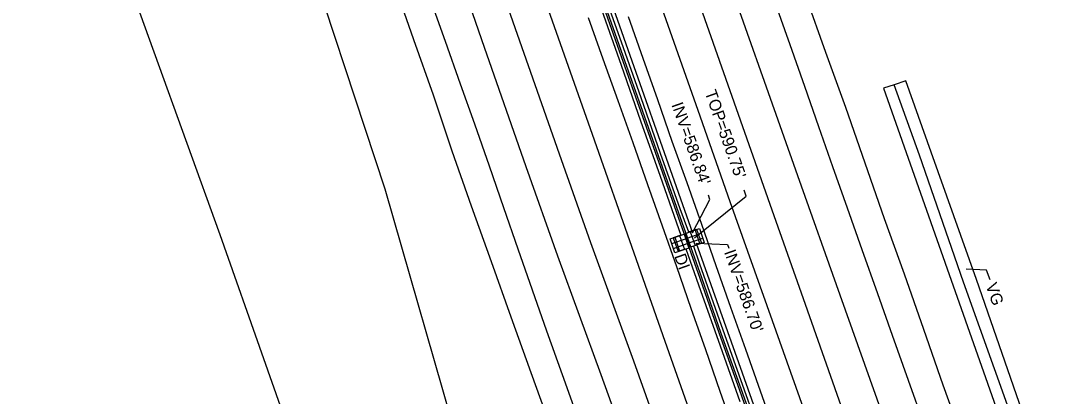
# Model space of a CAD drawing. Extents: x 2004847 to 2009016, y 1134161 to 1140101.
# Drawn here: x 2005569.8 to 2005919.4, y 1137430.7 to 1137558.5 of the extents above; entities that cross this region are included whole.
import ezdxf

# ---------------------------------------------------------------- set-up
doc = ezdxf.new("R2010")
doc.units = 0
for name, color, linetype in [('RD_EX_Conc', 7, 'Continuous'), ('RD_EX_DR_Inlet', 7, 'Continuous'), ('RD_EX_DR_Inlet_txCode', 7, 'Continuous'), ('RD_EX_DR_Pipe', 7, 'Continuous'), ('RD_EX_Fence_Other', 7, 'Continuous'), ('RD_EX_Pavement_Markings', 7, 'Continuous'), ('RD_EX_Road', 7, 'Continuous'), ('RD_EX_VEG', 7, 'Continuous'), ('RD_Sketch3', 7, 'Continuous')]:
    doc.layers.add(name, color=color, linetype=linetype)

msp = doc.modelspace()

# ---------------------------------------------------------------- linework, layer by layer
at = {"layer": 'RD_EX_Conc'}
for points in [[(2005680.52, 1137810.28), (2005687.18, 1137791.43), (2005693.85, 1137772.58), (2005700.54, 1137753.73), (2005707.21, 1137734.88), (2005713.85, 1137716.01), (2005720.48, 1137697.14), (2005727.14, 1137678.29), (2005733.79, 1137659.43), (2005740.49, 1137640.59), (2005747.16, 1137621.74), (2005753.85, 1137602.89), (2005760.49, 1137584.03), (2005767.18, 1137565.18), (2005773.87, 1137546.33), (2005780.5, 1137527.47), (2005787.18, 1137508.62), (2005793.87, 1137489.77), (2005800.53, 1137470.92), (2005807.19, 1137452.06), (2005813.89, 1137433.22), (2005820.56, 1137414.37)], [(2005681.18, 1137810.52), (2005687.84, 1137791.67), (2005694.51, 1137772.82), (2005701.21, 1137753.96), (2005707.88, 1137735.11), (2005714.51, 1137716.25), (2005721.16, 1137697.38), (2005727.78, 1137678.52), (2005734.42, 1137659.66), (2005741.13, 1137640.82), (2005747.79, 1137621.96), (2005754.44, 1137603.1), (2005761.08, 1137584.24), (2005767.77, 1137565.39), (2005774.43, 1137546.53), (2005781.07, 1137527.67), (2005787.74, 1137508.82), (2005794.43, 1137489.97), (2005801.1, 1137471.13), (2005807.76, 1137452.26), (2005814.47, 1137433.43), (2005821.16, 1137414.58)], [(2005966.12, 1137270.11), (2005960.31, 1137284.97), (2005945.18, 1137326.1), (2005939.36, 1137342.34), (2005925.51, 1137382.31), (2005910.14, 1137425.7), (2005894.53, 1137470.45), (2005879.23, 1137513.74), (2005870.52, 1137538.02), (2005866.6, 1137536.67), (2005863.03, 1137535.48)], [(2005863.03, 1137535.48), (2005871.4, 1137511.75), (2005886.7, 1137468.35), (2005902.54, 1137423.33), (2005917.98, 1137379.04), (2005930.59, 1137344.77), (2005930.07, 1137344.38), (2005930.61, 1137342.05), (2005930.73, 1137340.06), (2005932.46, 1137338.07), (2005937.59, 1137323.83), (2005952.48, 1137282.46), (2005970.17, 1137237.5), (2005987.63, 1137193.19), (2006006.12, 1137147.67), (2006025.01, 1137102.92)]]:
    msp.add_lwpolyline(points, dxfattribs=at)
at = {"layer": 'RD_EX_DR_Inlet'}
for p, q in [((2005797.35, 1137486.7), (2005798.97, 1137481.98)), ((2005798.95, 1137487.26), (2005800.58, 1137482.53)), ((2005791.03, 1137482.67), (2005795.76, 1137484.29)), ((2005792.09, 1137484.83), (2005793.71, 1137480.1)), ((2005793.69, 1137485.38), (2005795.32, 1137480.65)), ((2005796.29, 1137484.55), (2005801.02, 1137486.17)), ((2005796.84, 1137482.94), (2005801.57, 1137484.56)), ((2005791.58, 1137481.06), (2005796.31, 1137482.69))]:
    msp.add_line(p, q, dxfattribs=at)
for points in [[(2005797.36, 1137481.42), (2005795.74, 1137486.15), (2005800.47, 1137487.78), (2005802.09, 1137483.05)], [(2005792.1, 1137479.55), (2005790.48, 1137484.28), (2005795.21, 1137485.9), (2005796.83, 1137481.17)]]:
    msp.add_lwpolyline(points, close=True, dxfattribs=at)
at = {"layer": 'RD_EX_DR_Inlet_txCode'}
for points in [[(2005798.74, 1137484.62), (2005816.32, 1137498.83), (2005815.62, 1137500.8)], [(2005798.12, 1137486.36), (2005804.03, 1137497.65), (2005803.52, 1137499.1)], [(2005799.38, 1137482.87), (2005810.03, 1137482.31), (2005810.44, 1137481.16)]]:
    msp.add_lwpolyline(points, dxfattribs=at)
at = {"layer": 'RD_EX_DR_Pipe'}
for p, q in [((2005736.5, 1137660.69), (2005798.12, 1137486.36)), ((2005799.38, 1137482.87), (2005860.99, 1137308.79))]:
    msp.add_line(p, q, dxfattribs=at)
at = {"layer": 'RD_EX_Fence_Other'}
msp.add_lwpolyline([(2005544.1, 1137747.93), (2005571.98, 1137669.9), (2005603.8, 1137579.06), (2005637.48, 1137485.82), (2005667.17, 1137401.41)], dxfattribs=at)
at = {"layer": 'RD_EX_Pavement_Markings'}
for points in [[(2005650.65, 1138023.79), (2005661.36, 1137993.16), (2005675.57, 1137952.57), (2005689.8, 1137912.08), (2005700.62, 1137881.25), (2005715.02, 1137840.66), (2005729.45, 1137800.21), (2005740.39, 1137769.42), (2005754.76, 1137728.86), (2005769.14, 1137688.32), (2005780.1, 1137657.44), (2005794.53, 1137616.94), (2005808.89, 1137576.39), (2005823.14, 1137536.02), (2005833.8, 1137505.87), (2005848.16, 1137465.29), (2005862.54, 1137424.75)], [(2005638.93, 1138020.85), (2005649.77, 1137989.86), (2005663.98, 1137949.28), (2005678.2, 1137908.74), (2005692.41, 1137868.56), (2005702.98, 1137838.35), (2005717.35, 1137797.86), (2005731.8, 1137757.37), (2005742.51, 1137727.22), (2005756.88, 1137686.7), (2005771.33, 1137646.14), (2005782.09, 1137615.98), (2005796.49, 1137575.39), (2005810.82, 1137534.74), (2005825.09, 1137494.13), (2005835.74, 1137463.95), (2005849.99, 1137423.41)], [(2005628.29, 1138015.02), (2005639.01, 1137984.69), (2005653.3, 1137944.12), (2005667.51, 1137903.59), (2005678.25, 1137873.06), (2005692.46, 1137832.47), (2005706.73, 1137791.91), (2005717.65, 1137761.23), (2005732.03, 1137720.7), (2005746.31, 1137680.15), (2005757.06, 1137649.63), (2005771.38, 1137609.11), (2005785.67, 1137568.57), (2005799.94, 1137528.08), (2005810.82, 1137497.03), (2005825.14, 1137456.53), (2005839.37, 1137416.27)], [(2005570.31, 1137995.12), (2005581.13, 1137964.85), (2005595.41, 1137924.24), (2005609.59, 1137883.9), (2005620.42, 1137853.23), (2005634.8, 1137812.65), (2005649.23, 1137771.98), (2005659.76, 1137741.51), (2005674.17, 1137700.87), (2005688.48, 1137660.47), (2005702.51, 1137620.29), (2005713.22, 1137590.13), (2005727.31, 1137549.48), (2005741.41, 1137508.86), (2005752.24, 1137478.53), (2005766.92, 1137438.17), (2005781.39, 1137397.9)], [(2005602.85, 1137974.8), (2005617.38, 1137933.98), (2005631.61, 1137893.38), (2005642.64, 1137862.53), (2005656.88, 1137821.85), (2005671.18, 1137781.44), (2005685.25, 1137741.64), (2005695.66, 1137711.54), (2005709.89, 1137671.3), (2005724.46, 1137631.01), (2005735.24, 1137600.65), (2005749.69, 1137560.37), (2005764.04, 1137519.84), (2005778.16, 1137479.48), (2005788.73, 1137449.51), (2005803, 1137409.01)], [(2005591.82, 1137970.6), (2005606.28, 1137929.97), (2005620.66, 1137889.23), (2005631.47, 1137858.16), (2005645.93, 1137817.63), (2005660.14, 1137777.13), (2005670.99, 1137746.52), (2005685.12, 1137705.8), (2005699.26, 1137665.03), (2005713.5, 1137624.72), (2005724.31, 1137594.45), (2005738.53, 1137553.85), (2005752.77, 1137513.17), (2005763.43, 1137483.09), (2005778, 1137442.79), (2005792.39, 1137402.39)], [(2005709.04, 1137565.47), (2005714.01, 1137551.5), (2005719.17, 1137537), (2005723.97, 1137523.38), (2005729, 1137509.08), (2005733.86, 1137494.98), (2005738.75, 1137480.93), (2005743.63, 1137466.9), (2005748.52, 1137453.05), (2005753.83, 1137438.14), (2005758.84, 1137424.24)], [(2005826.29, 1137564.04), (2005831.11, 1137550.32), (2005836.1, 1137536.21), (2005840.91, 1137522.51), (2005845.68, 1137508.9), (2005850.67, 1137494.81), (2005855.67, 1137480.71), (2005860.91, 1137465.72), (2005865.96, 1137451.58), (2005871.37, 1137436.25), (2005876.68, 1137421.3)], [(2005762.62, 1137559.58), (2005767.67, 1137545.48), (2005772.74, 1137531.29), (2005777.78, 1137517.03), (2005782.78, 1137502.79), (2005787.78, 1137488.76), (2005792.61, 1137474.91), (2005797.56, 1137460.69), (2005802.49, 1137446.63), (2005807.43, 1137432.5), (2005812.38, 1137418.28)], [(2005776.23, 1137559.83), (2005781.22, 1137545.69), (2005786.17, 1137531.63), (2005791.12, 1137517.53), (2005796.13, 1137503.44), (2005801.09, 1137489.28), (2005806.07, 1137475.19), (2005811.05, 1137461.04), (2005816.08, 1137446.78), (2005821.11, 1137432.56), (2005826.07, 1137418.43)]]:
    msp.add_lwpolyline(points, dxfattribs=at)
at = {"layer": 'RD_EX_Road'}
for points in [[(2005610.52, 1137816.19), (2005617.08, 1137797.34), (2005624.29, 1137778.69), (2005630.74, 1137759.78), (2005637.03, 1137740.75), (2005643.84, 1137721.93), (2005650.6, 1137703.09), (2005657.24, 1137684.23), (2005663.8, 1137665.35), (2005670.26, 1137646.48), (2005676.83, 1137627.61), (2005683.5, 1137608.76), (2005689.91, 1137589.74), (2005696.78, 1137570.94), (2005703.25, 1137552.03), (2005709.92, 1137533.21), (2005716.27, 1137514.25), (2005722.92, 1137495.46), (2005729.7, 1137476.61), (2005736.39, 1137457.72), (2005743.18, 1137438.88), (2005749.96, 1137420.02)], [(2005749.68, 1137811.68), (2005756.36, 1137792.83), (2005763.03, 1137773.97), (2005769.93, 1137755.22), (2005776.41, 1137736.28), (2005783.05, 1137717.42), (2005789.65, 1137698.51), (2005796.44, 1137679.72), (2005803.09, 1137660.84), (2005809.62, 1137641.96), (2005816.53, 1137623.21), (2005823.16, 1137604.35), (2005829.9, 1137585.5), (2005836.6, 1137566.64), (2005843.24, 1137547.8), (2005850.12, 1137529), (2005856.67, 1137510.13), (2005863.23, 1137491.24), (2005869.96, 1137472.36), (2005876.59, 1137453.53), (2005883.19, 1137434.67), (2005889.89, 1137415.79)], [(2005767.21, 1137570.06), (2005773.86, 1137551.21), (2005780.5, 1137532.35), (2005787.15, 1137513.47), (2005793.81, 1137494.64), (2005796.73, 1137486.64), (2005799.5, 1137487.61), (2005801.14, 1137482.78), (2005798.42, 1137481.79), (2005800.48, 1137475.77), (2005807.14, 1137456.92), (2005813.83, 1137438.07), (2005820.54, 1137419.24)], [(2005767.21, 1137562.21), (2005773.84, 1137543.32), (2005780.47, 1137524.43), (2005787.14, 1137505.57), (2005794.14, 1137485.55), (2005791.56, 1137484.66), (2005791.8, 1137484), (2005792.81, 1137481.27), (2005793.26, 1137480.05), (2005795.85, 1137480.88), (2005800.86, 1137466.71), (2005807.53, 1137447.86), (2005814.19, 1137429)], [(2006028.69, 1137104.26), (2006009.81, 1137149.14), (2005991.28, 1137194.77), (2005973.8, 1137238.79), (2005956.71, 1137283.48), (2005941.45, 1137325.02), (2005933.78, 1137340.38), (2005921.69, 1137380.77), (2005906.28, 1137424.59), (2005890.2, 1137469.59), (2005875.19, 1137512.75), (2005866.6, 1137536.67)]]:
    msp.add_lwpolyline(points, dxfattribs=at)
at = {"layer": 'RD_EX_VEG'}
msp.add_lwpolyline([(2005718.89, 1137413.27), (2005693.64, 1137501.22), (2005662.96, 1137594.49), (2005634.34, 1137681.77)], dxfattribs=at)
at = {"layer": 'RD_Sketch3'}
msp.add_lwpolyline([(2005899.19, 1137470.35), (2005898.01, 1137473.69), (2005891.07, 1137473.98)], dxfattribs=at)

# ---------------------------------------------------------------- texts
at = {"layer": 'RD_EX_DR_Inlet_txCode'}
for s, p in [("TOP=590.75'", (2005802.21, 1137534.09)), ("INV=586.84'", (2005790.88, 1137529.91)), ("INV=586.70'", (2005808.76, 1137479.81)), ('DI', (2005791.84, 1137478.43))]:
    msp.add_text(s, height=4, rotation=289.4494, dxfattribs=at).set_placement(p)
at = {"layer": 'RD_Sketch3'}
msp.add_text('VG', height=4, rotation=289.4494, dxfattribs=at).set_placement((2005897.63, 1137468.49))

doc.saveas('drawing.dxf')
